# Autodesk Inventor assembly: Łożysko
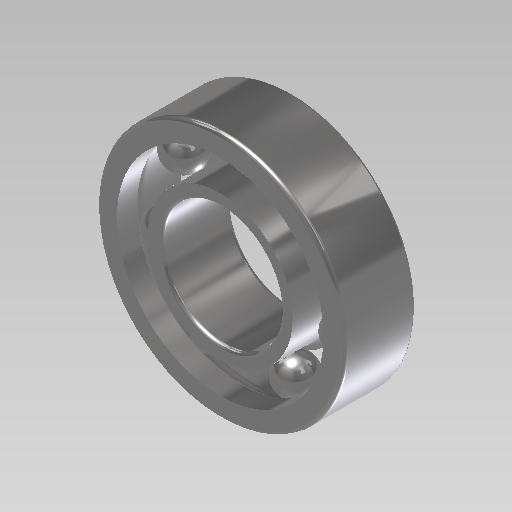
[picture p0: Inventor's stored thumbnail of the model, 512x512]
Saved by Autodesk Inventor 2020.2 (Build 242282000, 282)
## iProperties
Created: 2014-10
Part Number: Łożysko
Document SubType Name: Assembly
Designer: F.Stasiak
Catalog Web Link: www.expertbooks.pl
ClientObjectVersion: 1
Manager: www.cadconsulting.pl
Company: Fabian Stasiak CAD Consulting
Author: F.Stasiak
Subject: Zbiór ćwiczeń. Autodesk Inventor 2020. Kurs Professional
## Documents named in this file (2)
- C:\2020_Kurs_Professional\R3 Dynamika\AIR_100\Design Accelerator\Łożysko3.iam
- C:\2020_Kurs_Professional\Zasoby\ContentCenter\pl-PL\DIN 628 SKF(4)\DIN 628 SKF - SKF 7205 BE.ipt
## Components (1 placed, 1 different names)
1. DIN 628 SKF SKF 7205 BE:1
